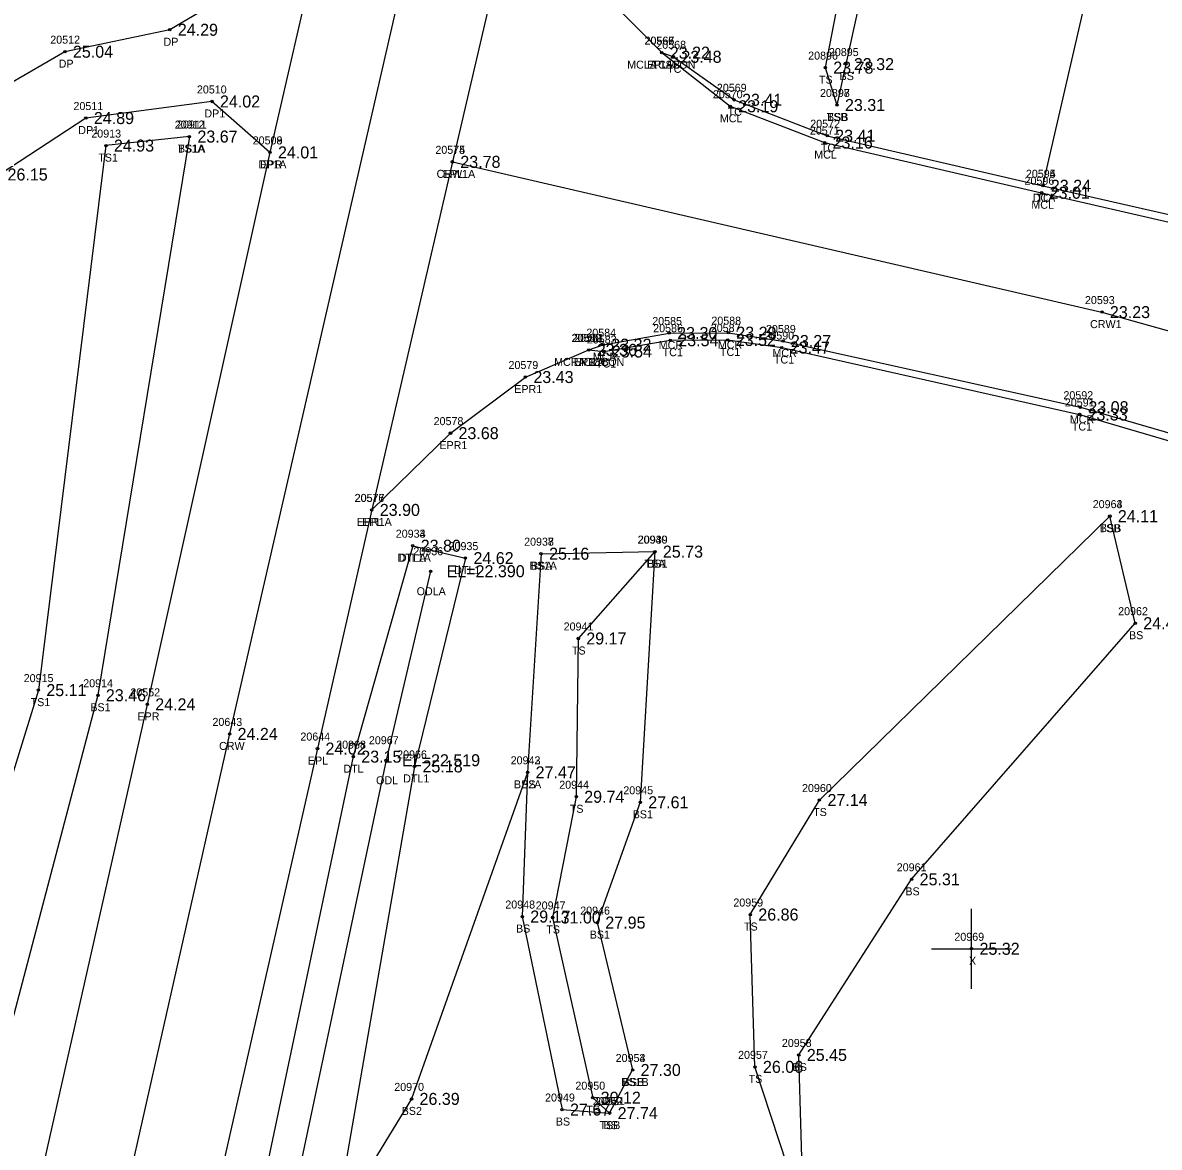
# Model space of a CAD drawing. Extents: x 2655177 to 2656219, y 761780 to 764748.
# Drawn here: x 2655568.1 to 2655710.1, y 762658.8 to 762799.3 of the extents above; entities that cross this region are included whole.
import ezdxf

# ---------------------------------------------------------------- set-up
doc = ezdxf.new("R2010")
doc.units = 0
for name, color, linetype in [('RD_DTM_BkLn1', 7, 'Continuous'), ('RD_DTM_BkLn2', 7, 'Continuous'), ('RD_DTM_BkLn_txCode', 7, 'Continuous'), ('RD_EX_Conc', 7, 'Continuous'), ('RD_EX_Conc_txCode', 7, 'Continuous'), ('RD_EX_Driveway', 7, 'Continuous'), ('RD_EX_Driveway_txCode', 7, 'Continuous'), ('RD_EX_H2O', 7, 'Continuous'), ('RD_EX_H2O_txCode', 7, 'Continuous'), ('RD_EX_Misc', 7, 'Continuous'), ('RD_EX_Misc_txCode', 7, 'Continuous'), ('RD_EX_Road', 7, 'Continuous'), ('RD_EX_Road_txCode', 7, 'Continuous'), ('RD_EX_TX_Conc_ELEV', 7, 'Continuous'), ('RD_EX_TX_Driveway_ELEV', 7, 'Continuous'), ('RD_EX_TX_H2O_ELEV', 7, 'Continuous'), ('RD_EX_TX_Misc_ELEV', 7, 'Continuous'), ('RD_EX_TX_Road_ELEV', 7, 'Continuous'), ('RD_HC_Survey_ELEV', 7, 'Continuous'), ('RD_HC_Survey_txCode', 7, 'Continuous'), ('RD_SMD_Locator', 7, 'Continuous')]:
    doc.layers.add(name, color=color, linetype=linetype)

msp = doc.modelspace()

# ---------------------------------------------------------------- linework, layer by layer
at = {"layer": 'RD_DTM_BkLn1'}
for points in [[(2655711.06, 763230.3), (2655703.38, 763195.9), (2655681.97, 763099.65), (2655659.44, 762998.39), (2655637.72, 762903.26), (2655615.94, 762806.28), (2655593.94, 762710.45), (2655572.67, 762616.37), (2655551.12, 762519.58), (2655528.83, 762422.13), (2655507.58, 762326.81), (2655486.01, 762234.2), (2655464.77, 762141.12), (2655442.2, 762047.28), (2655420.99, 761952.95), (2655398.79, 761855.74), (2655384.11, 761791.21)], [(2655621.78, 762781.91), (2655702.96, 762763.14), (2655749.84, 762750.03), (2655792.21, 762726.12)]]:
    msp.add_lwpolyline(points, dxfattribs=at)
at = {"layer": 'RD_DTM_BkLn2'}
for points in [[(2655665.76, 762827.13), (2655671.3, 762808.75), (2655668.39, 762793.68), (2655669.85, 762789.01)], [(2655665.76, 762827.13), (2655674.19, 762808.88), (2655670.96, 762794.12), (2655669.85, 762789.01)], [(2655647.95, 762795.55), (2655649.41, 762795.03), (2655656.99, 762789.66), (2655668.63, 762785.17), (2655695.58, 762778.92), (2655712.63, 762775.04), (2655737.36, 762768.55), (2655755.08, 762761.87), (2655757.75, 762760.7), (2655786.58, 762745.49), (2655788.64, 762744.27), (2655801.11, 762735.54)], [(2655588.92, 762785.07), (2655578.49, 762783.94), (2655570.04, 762715.92), (2655541.51, 762623.69), (2655540.45, 762599.84), (2655543.53, 762594.17)], [(2655588.92, 762785.07), (2655577.48, 762715.28), (2655552.42, 762620.33), (2655550.2, 762611.41)], [(2655638.83, 762758.42), (2655640.71, 762758.22), (2655649.02, 762759.63), (2655656.2, 762759.66), (2655662.94, 762758.71), (2655700.16, 762750.35), (2655744.25, 762737.41), (2655772.16, 762722.6), (2655773.58, 762721.61), (2655775.59, 762720.26), (2655783.79, 762714.41), (2655789.33, 762710.11)], [(2655665.68, 762650.38), (2655659.6, 762668.86), (2655659.02, 762687.89), (2655667.66, 762702.19), (2655703.95, 762737.65)], [(2655665.68, 762650.38), (2655665.08, 762670.35), (2655679.18, 762692.29), (2655707.13, 762724.28), (2655703.95, 762737.65)], [(2655632.87, 762732.96), (2655631.19, 762705.65), (2655630.52, 762687.64), (2655635.49, 762663.53), (2655641.44, 762663.08), (2655644.31, 762668.47)], [(2655632.87, 762732.96), (2655647.09, 762733.22), (2655645.27, 762701.91), (2655639.9, 762686.88), (2655644.31, 762668.47)], [(2655647.09, 762733.22), (2655637.52, 762722.37), (2655637.26, 762702.6), (2655634.31, 762687.52), (2655639.32, 762665.01), (2655641.44, 762663.08)], [(2655631.19, 762705.65), (2655616.68, 762664.86), (2655607.13, 762649.27)]]:
    msp.add_lwpolyline(points, dxfattribs=at)
at = {"layer": 'RD_EX_Conc'}
for points in [[(2655695.58, 762778.92), (2655701.44, 762804.38), (2655697.59, 762810.88), (2655698.83, 762816.69)], [(2655647.95, 762795.55), (2655656.5, 762788.85), (2655668.3, 762784.32), (2655695.43, 762778.05), (2655712.44, 762774.14), (2655737.03, 762767.62), (2655754.84, 762760.94), (2655757.41, 762759.82), (2655785.93, 762744.56)], [(2655638.83, 762758.42), (2655640.65, 762759.07), (2655648.88, 762760.53), (2655656.27, 762760.57), (2655663.1, 762759.53), (2655700.27, 762751.26), (2655744.39, 762738.46), (2655772.67, 762723.5), (2655774.32, 762722.61)]]:
    msp.add_lwpolyline(points, dxfattribs=at)
at = {"layer": 'RD_EX_Driveway'}
for points in [[(2655605, 762809.37), (2655586.47, 762798.41), (2655573.36, 762795.67), (2655559.24, 762787.47), (2655545.04, 762765.33), (2655541.01, 762760.72), (2655533.69, 762755.14), (2655505.04, 762752.17)], [(2655598.99, 762783.09), (2655591.74, 762789.45), (2655575.98, 762787.38), (2655565.19, 762780.33), (2655555.27, 762759.9), (2655550.24, 762730.01), (2655544.34, 762701.07), (2655531.32, 762637.94), (2655527.7, 762630.48), (2655527.21, 762614.18), (2655533.68, 762601.37), (2655541.26, 762592.29), (2655549.19, 762591.56), (2655556.36, 762593.84)]]:
    msp.add_lwpolyline(points, dxfattribs=at)
at = {"layer": 'RD_EX_H2O'}
for points in [[(2655616.83, 762733.96), (2655609.4, 762707.61), (2655588.37, 762607.98)], [(2655616.83, 762733.96), (2655623.42, 762732.41), (2655617.05, 762706.39), (2655607.13, 762649.27), (2655597.13, 762609.55), (2655592.83, 762601.92), (2655590.72, 762602.48), (2655588.85, 762603.42), (2655588.37, 762607.98)], [(2655619.06, 762730.77), (2655613.49, 762707.16), (2655591.84, 762605)]]:
    msp.add_lwpolyline(points, dxfattribs=at)
at = {"layer": 'RD_EX_Misc'}
for p, q in [((2655686.66, 762678.61), (2655686.66, 762688.61)), ((2655681.66, 762683.61), (2655691.66, 762683.61))]:
    msp.add_line(p, q, dxfattribs=at)
at = {"layer": 'RD_EX_Road'}
for points in [[(2655700.99, 763232.28), (2655693.55, 763198.57), (2655671.65, 763102.04), (2655649.04, 763001.06), (2655627.27, 762906.23), (2655605, 762809.37), (2655598.99, 762783.09), (2655583.65, 762714.14), (2655561.97, 762618.32), (2655556.36, 762593.84), (2655548.11, 762557.14), (2655540.1, 762522.48), (2655518.03, 762425.04), (2655496.48, 762329.56), (2655475.55, 762236.62), (2655473.2, 762226.14), (2655466.57, 762197.5), (2655460.06, 762168.16), (2655454.26, 762143.78), (2655432.5, 762049.88), (2655410.7, 761955.51), (2655388.17, 761858.43), (2655373.5, 761793.95)], [(2655722.66, 763227.87), (2655714.47, 763193.23), (2655692.89, 763097.26), (2655670.04, 762995.18), (2655648.57, 762900.67), (2655631.27, 762824.03), (2655626.67, 762802.87), (2655621.78, 762781.91), (2655611.71, 762738.43), (2655604.93, 762708.62), (2655582.64, 762610.54), (2655576.46, 762583.32), (2655561.41, 762517.24)], [(2655631.27, 762824.03), (2655634.69, 762812.94), (2655641.59, 762801.92), (2655647.95, 762795.55)], [(2655611.71, 762738.43), (2655621.55, 762748.02), (2655630.91, 762755.03), (2655638.83, 762758.42)]]:
    msp.add_lwpolyline(points, dxfattribs=at)
at = {"layer": 'RD_SMD_Locator'}
for centre in [(2655586.47, 762798.41), (2655573.36, 762795.67), (2655647.95, 762795.55), (2655647.95, 762795.55), (2655647.95, 762795.55), (2655649.41, 762795.03), (2655668.39, 762793.68), (2655670.96, 762794.12), (2655591.74, 762789.45), (2655656.99, 762789.66), (2655669.85, 762789.01), (2655669.85, 762789.01), (2655656.5, 762788.85), (2655575.98, 762787.38), (2655588.92, 762785.07), (2655588.92, 762785.07), (2655668.63, 762785.17), (2655578.49, 762783.94), (2655668.3, 762784.32), (2655598.99, 762783.09), (2655598.99, 762783.09), (2655621.78, 762781.91), (2655621.78, 762781.91), (2655695.43, 762778.05), (2655695.58, 762778.92), (2655695.58, 762778.92), (2655702.96, 762763.14), (2655648.88, 762760.53), (2655656.27, 762760.57), (2655649.02, 762759.63), (2655656.2, 762759.66), (2655663.1, 762759.53), (2655638.83, 762758.42), (2655638.83, 762758.42), (2655638.83, 762758.42), (2655640.65, 762759.07), (2655640.71, 762758.22), (2655662.94, 762758.71), (2655630.91, 762755.03), (2655700.27, 762751.26), (2655700.16, 762750.35), (2655621.55, 762748.02), (2655611.71, 762738.43), (2655611.71, 762738.43), (2655703.95, 762737.65), (2655703.95, 762737.65), (2655616.83, 762733.96), (2655616.83, 762733.96), (2655623.42, 762732.41), (2655632.87, 762732.96), (2655632.87, 762732.96), (2655647.09, 762733.22), (2655647.09, 762733.22), (2655619.06, 762730.77), (2655707.13, 762724.28), (2655637.52, 762722.37), (2655570.04, 762715.92), (2655577.48, 762715.28), (2655583.65, 762714.14), (2655593.94, 762710.45), (2655604.93, 762708.62), (2655609.4, 762707.61), (2655613.49, 762707.16), (2655617.05, 762706.39), (2655631.19, 762705.65), (2655631.19, 762705.65), (2655637.26, 762702.6), (2655645.27, 762701.91), (2655667.66, 762702.19), (2655679.18, 762692.29), (2655630.52, 762687.64), (2655634.31, 762687.52), (2655639.9, 762686.88), (2655659.02, 762687.89), (2655686.66, 762683.61), (2655665.08, 762670.35), (2655644.31, 762668.47), (2655644.31, 762668.47), (2655659.6, 762668.86), (2655616.68, 762664.86), (2655639.32, 762665.01), (2655635.49, 762663.53), (2655641.44, 762663.08), (2655641.44, 762663.08)]:
    msp.add_circle(centre, 0.15, dxfattribs=at)

# ---------------------------------------------------------------- texts
at = {"layer": 'RD_DTM_BkLn_txCode'}
for s, p in [('20896', (2655666.25, 762794.68)), ('20895', (2655668.84, 762795.12)), ('TS', (2655667.6, 762791.68)), ('BS', (2655670.18, 762792.12)), ('20897', (2655667.73, 762790.01)), ('20898', (2655667.73, 762790.01)), ('TSB', (2655668.59, 762787.01)), ('BSB', (2655668.6, 762787.01)), ('20912', (2655587.09, 762786.07)), ('20911', (2655587.37, 762786.07)), ('20913', (2655576.66, 762784.94)), ('TS1A', (2655587.48, 762783.07)), ('BS1A', (2655587.49, 762783.07)), ('TS1', (2655577.53, 762781.94)), ('20963', (2655701.81, 762738.65)), ('20964', (2655701.81, 762738.65)), ('TSB', (2655702.68, 762735.65)), ('BSB', (2655702.7, 762735.65)), ('20940', (2655644.93, 762734.22)), ('20939', (2655644.97, 762734.22)), ('20937', (2655630.75, 762733.96)), ('20938', (2655630.75, 762733.96)), ('BS1A', (2655631.43, 762730.96)), ('BSA', (2655631.6, 762730.96)), ('TSA', (2655645.8, 762731.22)), ('BS1', (2655646.14, 762731.22)), ('20962', (2655704.99, 762725.28)), ('20941', (2655635.69, 762723.37)), ('BS', (2655706.35, 762722.28)), ('TS', (2655636.73, 762720.37)), ('20915', (2655568.21, 762716.92)), ('20914', (2655575.65, 762716.28)), ('TS1', (2655569.08, 762713.92)), ('BS1', (2655576.54, 762713.28)), ('20942', (2655629.07, 762706.65)), ('20943', (2655629.07, 762706.65)), ('BS2A', (2655629.48, 762703.65)), ('BS', (2655630.41, 762703.65)), ('20944', (2655635.14, 762703.6)), ('20945', (2655643.15, 762702.91)), ('20960', (2655665.48, 762703.19)), ('TS', (2655636.46, 762700.6)), ('TS', (2655666.87, 762700.19)), ('BS1', (2655644.32, 762699.91)), ('20961', (2655677.32, 762693.29)), ('BS', (2655678.4, 762690.29)), ('20948', (2655628.4, 762688.64)), ('20959', (2655656.9, 762688.89)), ('20947', (2655632.2, 762688.52)), ('20946', (2655637.76, 762687.88)), ('TS', (2655658.23, 762685.89)), ('BS', (2655629.74, 762685.64)), ('TS', (2655633.52, 762685.52)), ('BS1', (2655638.95, 762684.88)), ('20958', (2655662.96, 762671.35)), ('20953', (2655642.19, 762669.47)), ('20954', (2655642.19, 762669.47)), ('20957', (2655657.49, 762669.86)), ('BS', (2655664.3, 762668.35)), ('20950', (2655637.16, 762666.01)), ('BS1B', (2655642.89, 762666.47)), ('BSB', (2655643.06, 762666.47)), ('TS', (2655658.81, 762666.86)), ('20970', (2655614.52, 762665.86)), ('20949', (2655633.37, 762664.53)), ('20952', (2655639.33, 762664.08)), ('20951', (2655639.61, 762664.08)), ('BS2', (2655615.45, 762662.86)), ('TS', (2655638.52, 762663.01)), ('BS', (2655634.71, 762661.53)), ('TSB', (2655640.18, 762661.08)), ('BS', (2655640.66, 762661.08))]:
    msp.add_text(s, height=1, dxfattribs=at).set_placement(p)
at = {"layer": 'RD_EX_Conc_txCode'}
for s, p in [('20566', (2655645.78, 762796.55)), ('20567', (2655645.81, 762796.55)), ('20568', (2655647.27, 762796.03)), ('MCLA 18CON', (2655643.63, 762793.55)), ('TCA', (2655646.67, 762793.55)), ('TC', (2655648.62, 762793.03)), ('20570', (2655654.34, 762789.85)), ('20569', (2655654.84, 762790.66)), ('MCL', (2655655.21, 762786.85)), ('TC', (2655656.19, 762787.66)), ('20571', (2655666.46, 762785.32)), ('20572', (2655666.51, 762786.17)), ('TC', (2655667.84, 762783.17)), ('MCL', (2655667.01, 762782.32)), ('20594', (2655693.46, 762779.92)), ('20595', (2655693.46, 762779.92)), ('20596', (2655693.29, 762779.05)), ('DCA', (2655694.31, 762776.92)), ('TC', (2655694.78, 762776.92)), ('MCL', (2655694.14, 762776.05)), ('20585', (2655646.76, 762761.53)), ('20588', (2655654.15, 762761.57)), ('20584', (2655638.53, 762760.07)), ('20586', (2655646.88, 762760.63)), ('20587', (2655654.08, 762760.66)), ('20590', (2655660.78, 762759.71)), ('20589', (2655660.98, 762760.53)), ('20582', (2655636.72, 762759.42)), ('20581', (2655637, 762759.42)), ('20583', (2655638.59, 762759.22)), ('MCR', (2655647.57, 762758.53)), ('MCR', (2655654.96, 762758.57)), ('MCR', (2655639.34, 762757.07)), ('TC1', (2655648.06, 762757.63)), ('TC1', (2655655.23, 762757.66)), ('MCR', (2655661.78, 762757.53)), ('MCRA 18CON', (2655634.5, 762756.42)), ('TC1A', (2655637.39, 762756.42)), ('TC1', (2655639.74, 762756.22)), ('TC1', (2655661.97, 762756.71)), ('20592', (2655698.15, 762752.26)), ('20591', (2655698.33, 762751.35)), ('MCR', (2655698.95, 762749.26)), ('TC1', (2655699.2, 762748.35))]:
    msp.add_text(s, height=1, dxfattribs=at).set_placement(p)
at = {"layer": 'RD_EX_Driveway_txCode'}
for s, p in [('20512', (2655571.53, 762796.67)), ('DP', (2655585.69, 762796.41)), ('DP', (2655572.58, 762793.67)), ('20510', (2655589.86, 762790.45)), ('20511', (2655574.43, 762788.38)), ('DP1', (2655590.79, 762787.45)), ('DP1', (2655575.03, 762785.38)), ('20509', (2655596.83, 762784.09)), ('DP1A', (2655597.56, 762781.09))]:
    msp.add_text(s, height=1, dxfattribs=at).set_placement(p)
at = {"layer": 'RD_EX_H2O_txCode'}
for s, p in [('20933', (2655614.71, 762734.96)), ('20934', (2655614.71, 762734.96)), ('20936', (2655616.91, 762732.77)), ('20935', (2655621.31, 762733.41)), ('DTL1A', (2655614.93, 762731.96)), ('DTLA', (2655615.1, 762731.96)), ('DTL1', (2655622.01, 762730.41)), ('ODLA', (2655617.32, 762727.77)), ('20968', (2655607.26, 762708.61)), ('20967', (2655611.35, 762709.16)), ('20966', (2655614.88, 762707.39)), ('DTL', (2655608.16, 762705.61)), ('DTL1', (2655615.64, 762704.39)), ('ODL', (2655612.25, 762704.16))]:
    msp.add_text(s, height=1, dxfattribs=at).set_placement(p)
at = {"layer": 'RD_EX_Misc_txCode'}
for s, p in [('20969', (2655684.52, 762684.61)), ('X', (2655686.35, 762681.61))]:
    msp.add_text(s, height=1, dxfattribs=at).set_placement(p)
at = {"layer": 'RD_EX_Road_txCode'}
for s, p in [('20565', (2655645.81, 762796.55)), ('EPL1B', (2655646.11, 762793.55)), ('20508', (2655596.83, 762784.09)), ('20574', (2655619.66, 762782.91)), ('EPR', (2655597.76, 762781.09)), ('EPL', (2655620.58, 762779.91)), ('20580', (2655636.68, 762759.42)), ('20579', (2655628.8, 762756.03)), ('EPR1B', (2655636.97, 762756.42)), ('EPR1', (2655629.52, 762753.03)), ('20578', (2655619.44, 762749.02)), ('EPR1', (2655620.16, 762746.02)), ('20576', (2655609.56, 762739.43)), ('20577', (2655609.59, 762739.43)), ('EPR1A', (2655609.82, 762736.43)), ('EPL', (2655610.5, 762736.43)), ('20552', (2655581.54, 762715.14)), ('EPR', (2655582.43, 762712.14)), ('20644', (2655602.79, 762709.62)), ('EPL', (2655603.73, 762706.62))]:
    msp.add_text(s, height=1, dxfattribs=at).set_placement(p)
at = {"layer": 'RD_EX_TX_Conc_ELEV'}
for s, p in [('23.22', (2655648.95, 762794.8)), ('23.22', (2655648.95, 762794.8)), ('23.48', (2655650.41, 762794.28)), ('23.19', (2655657.5, 762788.1)), ('23.41', (2655657.99, 762788.91)), ('23.16', (2655669.3, 762783.57)), ('23.41', (2655669.63, 762784.42)), ('23.24', (2655696.58, 762778.17)), ('23.24', (2655696.58, 762778.17)), ('23.01', (2655696.43, 762777.3)), ('23.30', (2655649.88, 762759.78)), ('23.29', (2655657.27, 762759.82)), ('23.32', (2655641.65, 762758.32)), ('23.54', (2655650.02, 762758.88)), ('23.52', (2655657.2, 762758.91)), ('23.47', (2655663.94, 762757.96)), ('23.27', (2655664.1, 762758.78)), ('23.36', (2655639.83, 762757.67)), ('23.36', (2655639.83, 762757.67)), ('23.54', (2655641.71, 762757.47)), ('23.33', (2655701.16, 762749.6)), ('23.08', (2655701.27, 762750.51))]:
    msp.add_text(s, height=1.5, dxfattribs=at).set_placement(p)
at = {"layer": 'RD_EX_TX_Driveway_ELEV'}
for s, p in [('24.29', (2655587.47, 762797.66)), ('25.04', (2655574.36, 762794.92)), ('24.02', (2655592.74, 762788.7)), ('24.89', (2655576.98, 762786.63)), ('24.01', (2655599.99, 762782.34)), ('26.15', (2655566.19, 762779.58))]:
    msp.add_text(s, height=1.5, dxfattribs=at).set_placement(p)
at = {"layer": 'RD_EX_TX_H2O_ELEV'}
for s, p in [('23.80', (2655617.83, 762733.21)), ('23.80', (2655617.83, 762733.21)), ('24.62', (2655624.42, 762731.66)), ('EL=22.390', (2655621.06, 762730.02)), ('23.15', (2655610.4, 762706.86)), ('EL=22.519', (2655615.49, 762706.41)), ('25.18', (2655618.05, 762705.64))]:
    msp.add_text(s, height=1.5, dxfattribs=at).set_placement(p)
at = {"layer": 'RD_EX_TX_Misc_ELEV'}
for s, p in [('23.32', (2655671.96, 762793.37)), ('23.78', (2655669.39, 762792.93)), ('23.31', (2655670.85, 762788.26)), ('23.31', (2655670.85, 762788.26)), ('23.67', (2655589.92, 762784.32)), ('23.67', (2655589.92, 762784.32)), ('24.93', (2655579.49, 762783.19)), ('24.11', (2655704.95, 762736.9)), ('24.11', (2655704.95, 762736.9)), ('25.16', (2655633.87, 762732.21)), ('25.16', (2655633.87, 762732.21)), ('25.73', (2655648.09, 762732.47)), ('25.73', (2655648.09, 762732.47)), ('24.46', (2655708.13, 762723.53)), ('29.17', (2655638.52, 762721.62)), ('25.11', (2655571.04, 762715.17)), ('23.46', (2655578.48, 762714.53)), ('27.47', (2655632.19, 762704.9)), ('27.47', (2655632.19, 762704.9)), ('29.74', (2655638.26, 762701.85)), ('27.61', (2655646.27, 762701.16)), ('27.14', (2655668.66, 762701.44)), ('25.31', (2655680.18, 762691.54)), ('29.17', (2655631.52, 762686.89)), ('31.00', (2655635.31, 762686.77)), ('26.86', (2655660.02, 762687.14)), ('27.95', (2655640.9, 762686.13)), ('25.32', (2655687.66, 762682.86)), ('25.45', (2655666.08, 762669.6)), ('27.30', (2655645.31, 762667.72)), ('27.30', (2655645.31, 762667.72)), ('26.06', (2655660.6, 762668.11)), ('26.39', (2655617.68, 762664.11)), ('30.12', (2655640.32, 762664.26)), ('27.67', (2655636.49, 762662.78)), ('27.74', (2655642.44, 762662.33)), ('27.74', (2655642.44, 762662.33))]:
    msp.add_text(s, height=1.5, dxfattribs=at).set_placement(p)
at = {"layer": 'RD_EX_TX_Road_ELEV'}
for s, p in [('23.22', (2655648.95, 762794.8)), ('24.01', (2655599.99, 762782.34)), ('23.78', (2655622.78, 762781.16)), ('23.36', (2655639.83, 762757.67)), ('23.43', (2655631.91, 762754.28)), ('23.68', (2655622.55, 762747.27)), ('23.90', (2655612.71, 762737.68)), ('23.90', (2655612.71, 762737.68)), ('24.24', (2655584.65, 762713.39)), ('24.02', (2655605.93, 762707.87))]:
    msp.add_text(s, height=1.5, dxfattribs=at).set_placement(p)
at = {"layer": 'RD_HC_Survey_ELEV'}
for s, p in [('23.78', (2655622.78, 762781.16)), ('23.23', (2655703.96, 762762.39)), ('24.24', (2655594.94, 762709.7))]:
    msp.add_text(s, height=1.5, dxfattribs=at).set_placement(p)
at = {"layer": 'RD_HC_Survey_txCode'}
for s, p in [('20575', (2655619.66, 762782.91)), ('CRW1A', (2655619.81, 762779.91)), ('20593', (2655700.84, 762764.14)), ('CRW1', (2655701.48, 762761.14)), ('20643', (2655591.8, 762711.45)), ('CRW', (2655592.63, 762708.45))]:
    msp.add_text(s, height=1, dxfattribs=at).set_placement(p)

doc.saveas('drawing.dxf')
